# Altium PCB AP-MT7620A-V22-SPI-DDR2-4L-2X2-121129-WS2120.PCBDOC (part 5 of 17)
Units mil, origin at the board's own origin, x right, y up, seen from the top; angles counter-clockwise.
Board outline 7316 x 4279 mil, 4 copper layers (Top, Inner Layer 2, Inner Layer 3, Bottom), stack 35.4 mil thick; 640 components, 473 nets, 2041 pads, 2358 vias.
Unrouted connection lines stored in the file: 11.
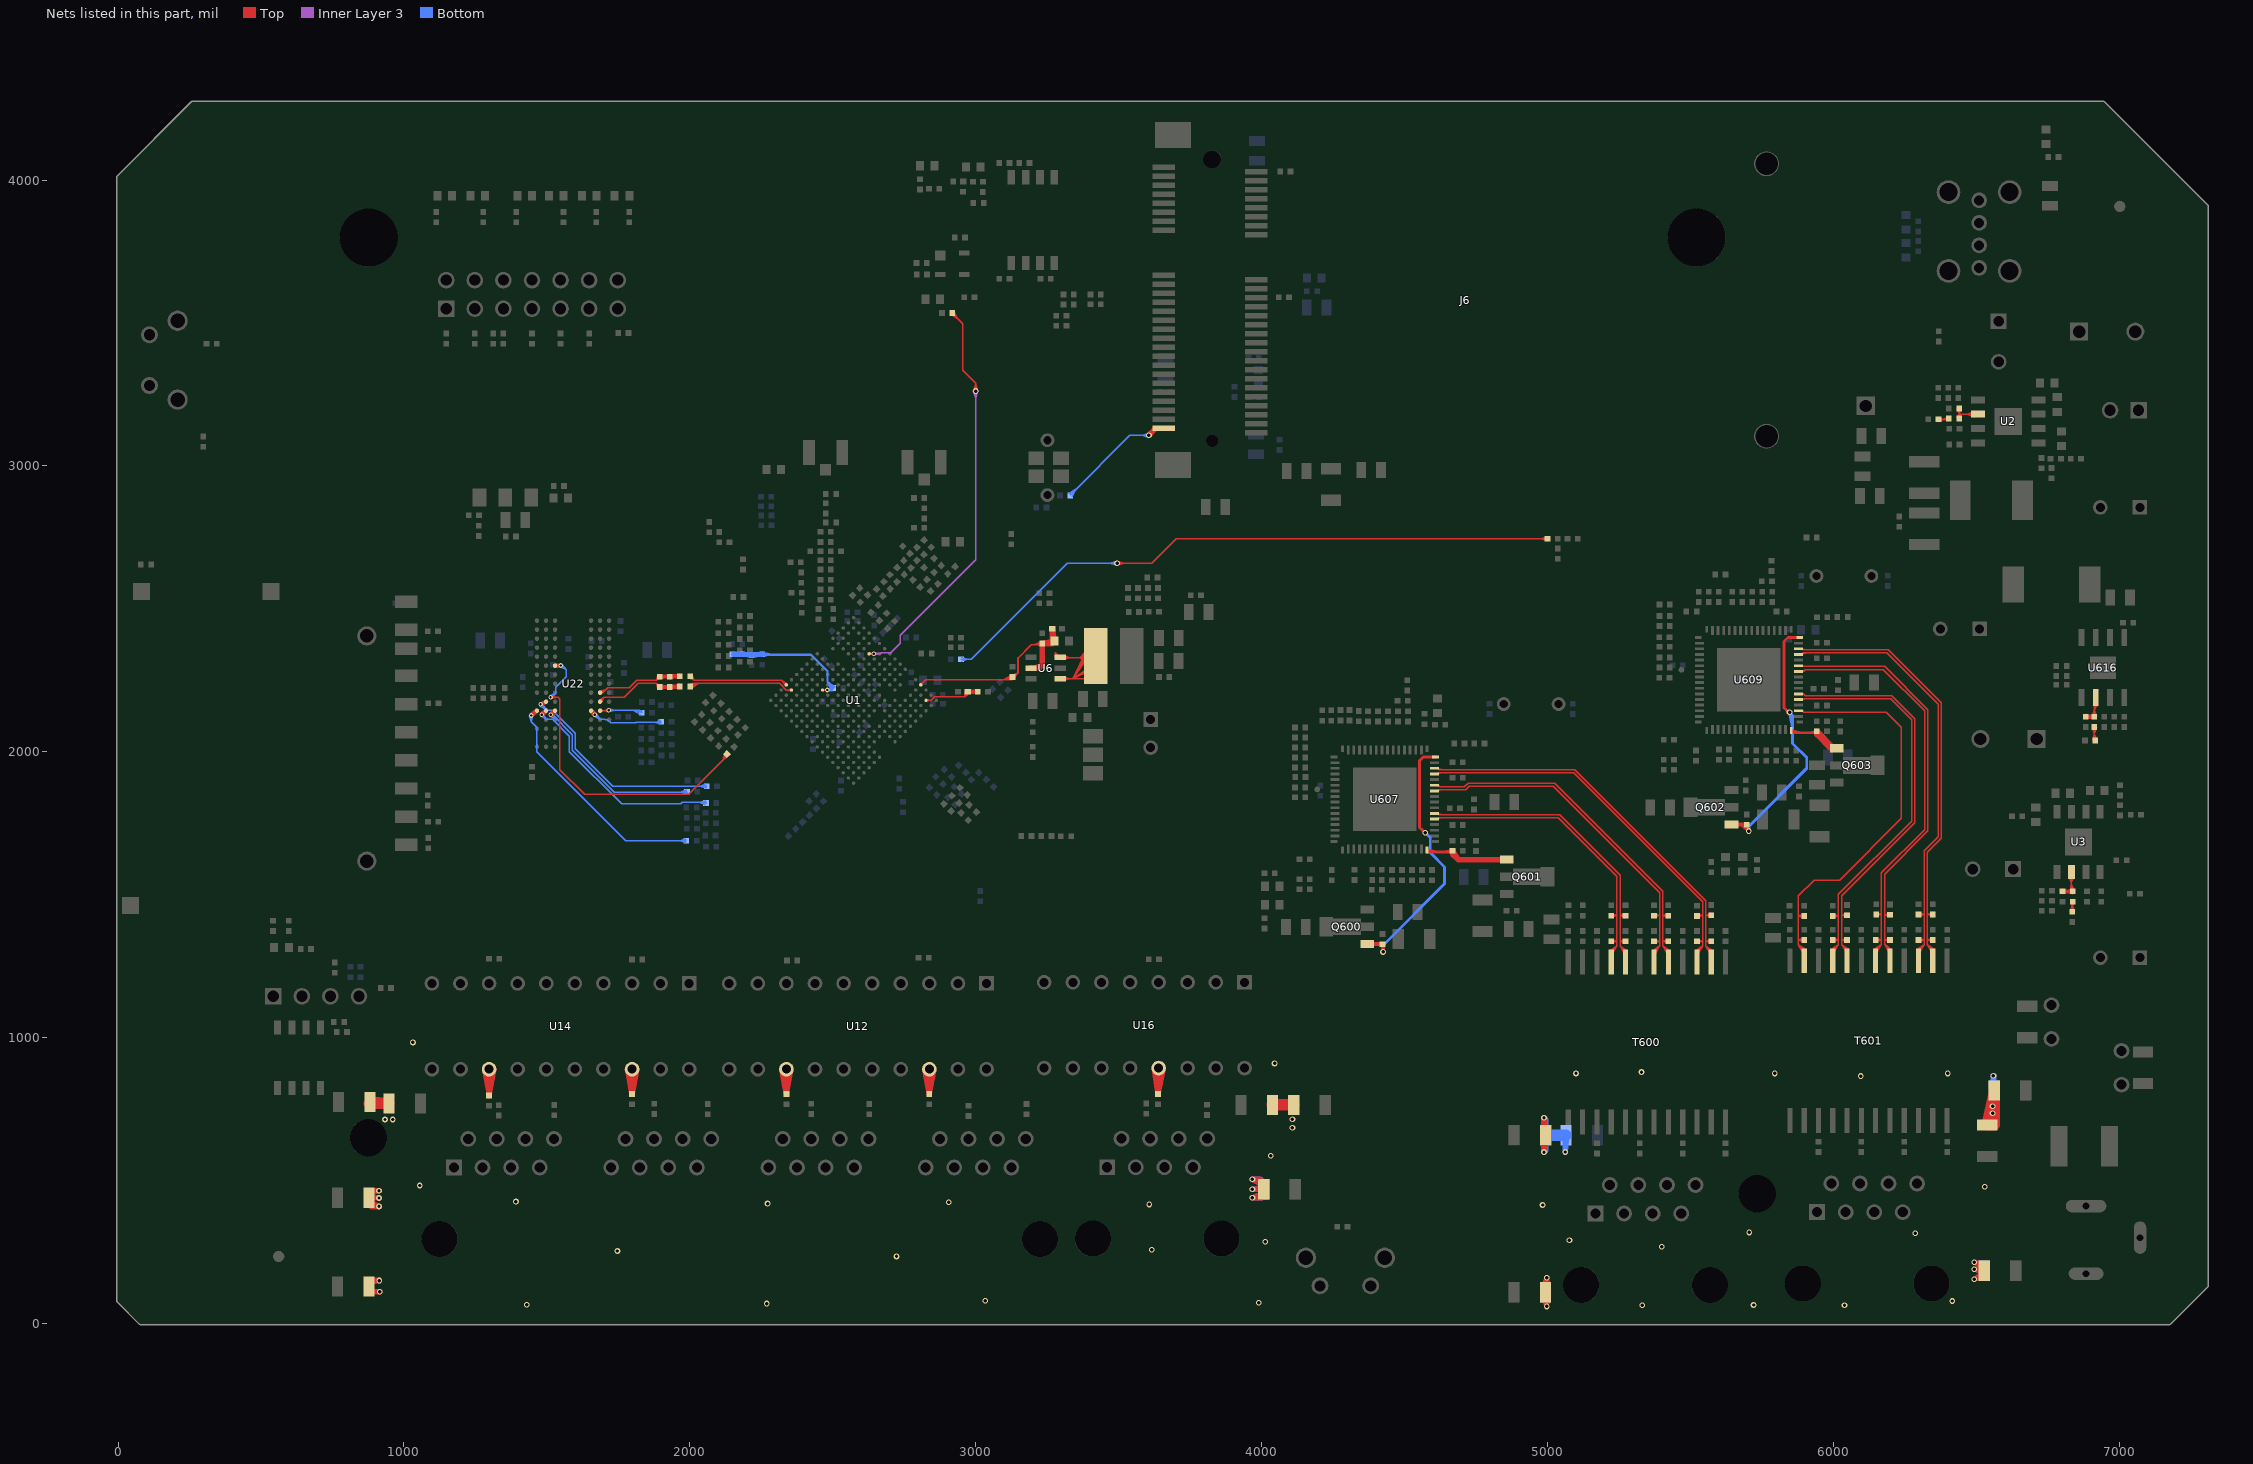
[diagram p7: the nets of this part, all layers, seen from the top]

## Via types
v1: diameter 20, hole 12, Top to Bottom, 2117 vias
v2: diameter 16, hole 8, Top to Bottom, 241 vias

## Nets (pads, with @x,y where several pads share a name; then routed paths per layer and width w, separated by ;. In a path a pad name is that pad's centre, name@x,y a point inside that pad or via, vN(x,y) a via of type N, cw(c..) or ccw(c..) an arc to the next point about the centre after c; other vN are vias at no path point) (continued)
CHANNEL_A-_2: C719.1 R792.2 T601.11 U609.19 | length 1668.2
  Top w5: U609.19@5878.22,2143.78 5892.22,2143.78 5897,2139 ; U609.19@5889.05,2143.78 5897,2139 ; T601.11@5892.8,1299.86 5878.05,1325.01 ; C719.1@5896.23,1418.71 5878.05,1427 ; R792.2@5896.28,1334.72 5878.05,1343.01 ; C719.1@5896.96,1433.43 5878.05,1427 ; R792.2@5897.02,1349.44 5878.05,1343.01 ; T601.11@5898.05,1269.54 5898.05,1305.01 5878.05,1325.01 ; T601.11@5898.05,1303.79 5878.05,1325.01 ; T601.11@5902.28,1308.79 5878.05,1325.01 ; 5878.05,1325.01 5878.05,1343.01 ; 5878.05,1343.01 5898.05,1343.01 R792.2@5898.05,1342.01 5878.05,1343.01 ; 5878.05,1343.01 5878.05,1427 ; 5878.05,1427 5898,1427 C719.1@5898,1426 5878.05,1427 ; 5878.05,1427 5878.05,1496.5 5932.55,1551 5938.55,1551 6021.76,1551 6238,1767.24 6238,2085.5 6184.5,2139 5897,2139
CHANNEL_B+: C708.1 R785.2 T600.9 U607.21 | length 1317.7
  Top w5: U607.21@4604.22,1765.15 4617.09,1765.15 4620.99,1769.05 ; 4635.41,1769.05 U607.21@4615.05,1765.15 ; T600.9@5218.82,1303.79 5243.05,1320.01 ; T600.9@5223.05,1264.54 5223.05,1300.01 5243.05,1320.01 ; T600.9@5223.05,1298.79 5243.05,1320.01 ; R785.2@5224.08,1344.44 5243.05,1338.01 ; C708.1@5224.08,1434.43 5243.05,1428 ; R785.2@5224.82,1329.72 5243.05,1338.01 ; C708.1@5224.82,1419.71 5243.05,1428 ; T600.9@5228.3,1294.86 5243.05,1320.01 ; U607.21@4615.05,1765.15 4620.99,1769.05 ; U607.21@4615.05,1765.15 4620.99,1769.05 ; 4620.99,1769.05 5037.99,1769.05 5243.05,1563.99 5243.05,1428 ; 5243.05,1320.01 5243.05,1338.01 ; 5243.05,1338.01 5223.05,1338.01 R785.2@5223.05,1337.01 5243.05,1338.01 ; 5243.05,1338.01 5243.05,1428 ; 5243.05,1428 5223.05,1428 C708.1@5223.05,1427 5243.05,1428
CHANNEL_B+_2: C720.1 R793.2 T601.9 U609.21 | length 1647.5
  Top w5: U609.21@5878.22,2183.15 5898.35,2183.15 ; U609.21@5889.05,2183.15 5898.35,2183.15 ; T601.9@5993.82,1308.79 6018.05,1325.01 ; T601.9@5998.05,1269.54 5998.05,1305.01 6018.05,1325.01 ; T601.9@5998.05,1303.79 6018.05,1325.01 ; C720.1@5999.03,1433.43 6018,1427 ; R793.2@5999.09,1349.44 6018,1343.01 ; C720.1@5999.77,1418.71 6018,1427 ; R793.2@5999.83,1334.72 6018,1343.01 ; T601.9@6003.3,1299.86 6018.05,1325.01 ; 5898.35,2183.15 5900.7,2185.5 6200.22,2185.5 6274,2111.72 6274,1757.06 6018.05,1501.1 6018.05,1500.05 6018,1500 6018,1427 ; 6018.02,1337.5 6018.05,1325.01 ; 6018.02,1337.5 6018,1343.01 ; 6018.02,1337.5 6018,1414.5 6018,1427 ; 6018,1343.01 5998.05,1343.01 R793.2@5998.05,1342.01 6018,1343.01 ; 6018,1427 5999,1427 C720.1@5998,1426 6018,1427
CHANNEL_B-: C709.1 R786.2 T600.8 U607.22 | length 1328.9
  Top w5: U607.22@4604.22,1784.84 4617.2,1784.84 4621.99,1780.05 ; 4635.63,1780.05 U607.22@4615.05,1784.84 ; T600.8@5267.7,1295.01 5254.05,1320.01 ; R786.2@5271.19,1329.74 5254.05,1338.01 ; C709.1@5271.19,1419.73 5254.05,1428 ; R786.2@5271.96,1344.43 5254.05,1338.01 ; C709.1@5271.96,1434.42 5254.05,1428 ; T600.8@5273.05,1264.54 5273.05,1301.01 5254.05,1320.01 ; T600.8@5273.05,1298.79 5254.05,1320.01 ; T600.8@5277.4,1303.7 5254.05,1320.01 ; U607.22@4615.05,1784.84 4621.99,1780.05 ; U607.22@4615.05,1784.84 4621.99,1780.05 ; 4621.99,1780.05 5042.55,1780.05 5254.05,1568.55 5254.05,1428 ; 5254.05,1320.01 5254.05,1338.01 ; 5254.05,1338.01 5273.05,1338.01 R786.2@5273.05,1337.01 5254.05,1338.01 ; 5254.05,1338.01 5254.05,1428 ; 5254.05,1428 5273.05,1428 C709.1@5273.05,1427 5254.05,1428
CHANNEL_B-_2: C721.1 R794.2 T601.8 U609.22 | length 1659
  Top w5: U609.22@5878.22,2202.84 5895.5,2202.84 ; T601.8@6042.7,1300.01 6029.05,1325.01 ; R794.2@6046.19,1334.74 6029.05,1343.01 ; C721.1@6046.52,1420.65 6029,1428 ; C721.1@6046.52,1435.35 6029,1428 ; R794.2@6046.96,1349.43 6029.05,1343.01 ; C721.1@6048,1428 6029,1428 ; T601.8@6048.05,1269.54 6048.05,1306.01 6029.05,1325.01 ; T601.8@6048.05,1303.79 6029.05,1325.01 ; T601.8@6052.4,1308.7 6029.05,1325.01 ; U609.22@5889.05,2202.84 5895.5,2202.84 ; U609.22@5889.05,2202.84 5901.84,2196.5 ; U609.22@5889.05,2202.84 5895.5,2202.84 ; 5895.5,2202.84 5901.84,2196.5 ; 5901.84,2196.5 6204.78,2196.5 6285,2116.28 6285,1752.5 6029,1496.5 6029,1428 ; 6029,1428 6029,1412.5 6029.05,1334 ; 6029.05,1325.01 6029.05,1334 ; 6029.05,1334 6029.05,1343.01 ; 6029.05,1343.01 6048.05,1343.01 R794.2@6048.05,1342.01 6029.05,1343.01
CHANNEL_C+: C710.1 R787.2 T600.6 U607.26 | length 1487
  Top w5: U607.26@4604.22,1863.58 4617.52,1863.58 4620.94,1867 ; 4635.24,1867 U607.26@4615.05,1863.58 ; T600.6@5368.69,1303.68 5393.05,1321.01 ; T600.6@5373.05,1264.54 5373.05,1301.01 5393.05,1321.01 ; T600.6@5373.05,1298.79 5393.05,1321.01 ; R787.2@5374.08,1344.44 5393.05,1338.01 ; C710.1@5374.08,1434.43 5393.05,1428 ; R787.2@5374.82,1329.72 5393.05,1338.01 ; C710.1@5374.82,1419.71 5393.05,1428 ; T600.6@5378.37,1294.96 5393.05,1321.01 ; U607.26@4615.05,1863.58 4620.94,1867 ; U607.26@4615.05,1863.58 4620.94,1867 ; 4620.94,1867 4714.02,1867 4727.02,1880 5020.4,1880 5393.05,1507.35 5393.05,1428 ; 5393.05,1321.01 5393.05,1338.01 ; 5393.05,1338.01 5373.05,1338.01 R787.2@5373.05,1337.01 5393.05,1338.01 ; 5393.05,1338.01 5393.05,1428 ; 5393.05,1428 5373.05,1428 C710.1@5373.05,1427 5393.05,1428
CHANNEL_C+_2: C722.1 R799.2 T601.6 U609.26 | length 1722
  Top w5: U609.26@5878.22,2281.58 5896.08,2281.58 ; T601.6@6143.68,1308.68 6168,1326 ; T601.6@6148.05,1269.54 6148.05,1306.05 6168,1326 ; T601.6@6148.05,1303.79 6168,1326 ; R799.2@6149.09,1349.44 6168,1343 ; R799.2@6149.82,1334.72 6168,1343 ; C722.1@6151.15,1438.41 6168,1432 ; C722.1@6151.96,1423.76 6168,1432 ; T601.6@6153.38,1299.97 6168,1326 ; U609.26@5889.05,2281.58 5896.08,2281.58 ; U609.26@5889.05,2281.58 5902.5,2288 ; U609.26@5889.05,2281.58 5896.08,2281.58 ; 5896.08,2281.58 5902.5,2288 ; 5902.5,2288 6175.47,2288 6320,2143.47 6320,1728.28 6168,1576.28 6168,1432 ; 6168,1326 6168,1343 ; 6168,1343 6148.05,1343.01 R799.2@6148.05,1342.01 6168,1343 ; 6168,1343 6168,1432 ; 6168,1432 6150,1432 C722.1@6150,1431 6168,1432
CHANNEL_C-: C711.1 R788.2 T600.5 U607.27 | length 1473.4
  Top w5: U607.27@4604.22,1883.26 4604.43,1883.05 4617.99,1883.05 4623.04,1878 ; U607.27@4615.05,1883.26 4623.04,1878 ; T600.5@5417.55,1295.22 5404.05,1322.01 ; R788.2@5421.19,1329.74 5404.05,1338.01 ; C711.1@5421.19,1419.73 5404.05,1428 ; R788.2@5421.96,1344.43 5404.05,1338.01 ; C711.1@5421.96,1434.42 5404.05,1428 ; T600.5@5423.05,1264.54 5423.05,1303.01 5404.05,1322.01 ; T600.5@5423.05,1298.79 5404.05,1322.01 ; T600.5@5427.64,1303.47 5404.05,1322.01 ; 4623.04,1878 4709.46,1878 4722.46,1891 5024.96,1891 5404.05,1511.91 5404.05,1428 ; 5404.05,1322.01 5404.05,1338.01 ; 5404.05,1338.01 5423.05,1338.01 R788.2@5423.05,1337.01 5404.05,1338.01 ; 5404.05,1338.01 5404.05,1428 ; 5404.05,1428 5423.05,1428 C711.1@5423.05,1427 5404.05,1428
CHANNEL_C-_2: C723.1 R800.2 T601.5 U609.27 | length 1741.2
  Top w5: U609.27@5878.22,2301.26 5878.43,2301.05 5891.99,2301.05 5894.04,2299 ; 5909.11,2299 U609.27@5889.05,2301.26 ; T601.5@6192.56,1300.21 6179,1327.06 ; C723.1@6196.13,1422.74 6179.05,1431 ; R800.2@6196.19,1334.74 6179,1343.01 ; C723.1@6196.91,1437.42 6179.05,1431 ; R800.2@6196.96,1349.43 6179,1343.01 ; T601.5@6198.05,1269.54 6198.05,1308.01 6179,1327.06 ; T601.5@6198.05,1303.79 6179,1327.06 ; T601.5@6202.64,1308.47 6179,1327.06 ; U609.27@5889.05,2301.26 5894.04,2299 ; U609.27@5889.05,2301.26 5894.04,2299 ; 5894.04,2299 6180.03,2299 6331,2148.03 6331,1723.72 6179,1571.72 6179,1430.95 ; 6179,1327.06 6179,1343.01 ; 6179,1343.01 6198.05,1343.01 R800.2@6198.05,1342.01 6179,1343.01 ; 6179,1343.01 6179,1430.95 ; 6179,1430.95 6179.05,1431 ; 6179.05,1431 6198,1431 C723.1@6198,1430 6179.05,1431
CHANNEL_D+: C712.1 R789.2 T600.3 U607.29 | length 1636.2
  Top w5: U607.29@4604.22,1922.63 4616,1922.63 4620.37,1927 ; 4635.52,1927 U607.29@4615.05,1922.63 ; T600.3@5518.69,1303.68 5543.05,1321.01 ; T600.3@5523.05,1264.54 5523.05,1301.01 5543.05,1321.01 ; T600.3@5523.05,1298.79 5543.05,1321.01 ; C712.1@5523.28,1433.49 5543.05,1429 ; R789.2@5524.08,1344.44 5543.05,1338.01 ; R789.2@5524.82,1329.72 5543.05,1338.01 ; C712.1@5525.46,1418.92 5543.05,1429 ; T600.3@5528.37,1294.96 5543.05,1321.01 ; U607.29@4615.05,1922.63 4620.37,1927 ; U607.29@4615.05,1922.63 4620.37,1927 ; 4620.37,1927 5091.5,1927 5543.05,1475.45 5543.05,1429 ; 5543.05,1321.01 5543.05,1338.01 ; 5543.05,1338.01 5523.05,1338.01 R789.2@5523.05,1337.01 5543.05,1338.01 ; 5543.05,1338.01 5543.05,1429 ; 5543.05,1429 5523,1429 C712.1@5523,1426 5543.05,1429
CHANNEL_D+_2: C724.1 R801.2 T601.3 U609.29 | length 1780.6
  Top w5: U609.29@5878.22,2340.63 5878.64,2341.05 5889.99,2341.05 5894.99,2346.05 ; 5909.78,2346.05 U609.29@5889.05,2340.63 ; T601.3@6293.69,1308.68 6318.05,1326.01 ; T601.3@6298.05,1269.54 6298.05,1306.01 6318.05,1326.01 ; T601.3@6298.05,1303.79 6318.05,1326.01 ; C724.1@6299.03,1438.43 6318.05,1432 ; R801.2@6299.08,1349.44 6318.05,1343.01 ; C724.1@6299.77,1423.71 6318.05,1432 ; R801.2@6299.82,1334.72 6318.05,1343.01 ; T601.3@6303.37,1299.96 6318.05,1326.01 ; U609.29@5889.05,2340.63 5894.99,2346.05 ; U609.29@5889.05,2340.63 5894.99,2346.05 ; 5894.99,2346.05 6187.67,2346.05 6367,2166.72 6367,1702.5 6318.05,1653.55 6318.05,1432 ; 6318.05,1326.01 6318.05,1343.01 ; 6318.05,1343.01 6318.05,1432 ; 6318.05,1343.01 6298.05,1343.01 R801.2@6298.05,1342.01 6318.05,1343.01 ; 6318.05,1432 6298,1432 C724.1@6298,1431 6318.05,1432
CHANNEL_D-: C713.1 R790.2 T600.2 U607.30 | length 1640.4
  Top w5: U607.30@4604.22,1942.32 4604.95,1943.05 4615.99,1943.05 4621.04,1938 ; 4635.51,1938 U607.30@4615.05,1942.32 ; T600.2@5567.7,1295.01 5554.05,1320.01 ; C713.1@5571.13,1420.74 5554.05,1429 ; R790.2@5571.19,1329.74 5554.05,1338.01 ; C713.1@5571.91,1435.42 5554.05,1429 ; R790.2@5571.96,1344.43 5554.05,1338.01 ; T600.2@5573.05,1264.54 5573.05,1301.01 5554.05,1320.01 ; T600.2@5573.05,1298.79 5554.05,1320.01 ; T600.2@5577.4,1303.7 5554.05,1320.01 ; U607.30@4615.05,1942.32 4621.04,1938 ; U607.30@4615.05,1942.32 4621.04,1938 ; 4621.04,1938 5096.06,1938 5554.05,1480.01 5554.05,1477.78 5554.05,1429 ; 5554.05,1320.01 5554.05,1338.01 ; 5554.05,1338.01 5573.05,1338.01 R790.2@5573.05,1337.01 5554.05,1338.01 ; 5554.05,1338.01 5554.05,1429 ; 5554.05,1429 5573,1429 C713.1@5573,1428 5554.05,1429
CHANNEL_D-_2: C725.1 R802.2 T601.2 U609.30 | length 1780.3
  Top w5: U609.30@5878.22,2360.32 5878.95,2361.05 5889.99,2361.05 5893.99,2357.05 ; 5909.27,2357.05 U609.30@5889.05,2360.32 ; T601.2@6342.7,1300.01 6329.05,1325.01 ; C725.1@6346.13,1423.74 6329.05,1432 ; R802.2@6346.19,1334.74 6329.05,1343.01 ; C725.1@6346.91,1438.42 6329.05,1432 ; R802.2@6346.96,1349.43 6329.05,1343.01 ; T601.2@6348.05,1269.54 6348.05,1306.01 6329.05,1325.01 ; T601.2@6348.05,1303.79 6329.05,1325.01 ; T601.2@6352.4,1308.7 6329.05,1325.01 ; U609.30@5889.05,2360.32 5893.99,2357.05 ; U609.30@5889.05,2360.32 5893.99,2357.05 ; 5893.99,2357.05 6192.23,2357.05 6378,2171.28 6378,1699.1 6378,1697.94 6329.05,1648.99 6329.05,1432 ; 6329.05,1325.01 6329.05,1343.01 ; 6329.05,1343.01 6348.05,1343.01 R802.2@6348.05,1342.01 6329.05,1343.01 ; 6329.05,1343.01 6329.05,1432 ; 6329.05,1432 6348,1432 C725.1@6348,1431 6329.05,1432
CHGND: C113.2 C116.2 C117.2 C118.2 C119.2 C120.2 C122.2 C123.2 | length 1295.6
  Top w20: C122.2@878.12,114.25 v1(915.5,111.5) 878.12,111.5 C122.2@878.12,123.9 ; C122.2@878.12,130 C122.2@878.12,123.9 ; C122.2@878.12,145.75 v1(914,150.5) 881.7,150.5 878.12,146.92 C122.2@878.12,123.9 ; C116.2@878.12,424.25 v1(913,410) 887,410 887,431.12 C116.2@878.12,440 ; C116.2@878.12,455.75 v1(913,465) 884.5,465 878.12,458.62 C116.2@878.12,440 ; C120.2@878.12,770 878.12,772 C120.2@881.62,775.5 ; v1(913,439.5) 908,440 C116.2@878.12,440 ; C117.2@4007.88,454.25 v1(3968,440) 4000.3,440 C117.2@4000.3,470 ; C117.2@4007.88,485.75 v1(3968,505) 3991.7,505 4007.88,488.82 C117.2@4007.88,470 ; C117.2@4000.3,470 C117.2@4007.88,470 ; C117.2@4000.3,470 v1(3968,470) C117.2@4007.88,470
  Top w40: C120.2@878.12,770 C113.2@947.88,770 C120.2@881.62,775.5 ; C123.2@4038.12,765 C119.2@4112.88,765 C123.2@4038.12,765
  Bottom w20: C118.2@4007.88,454.25 v1(3968,440) 4000.6,440 4005.11,444.51 C118.2@4005.11,470 ; C118.2@4007.88,485.75 v1(3968,505) 3996.5,505 C118.2@3996.5,470 ; C118.2@3996.5,470 v1(3968,470) C118.2@4007.88,470 C118.2@4005.11,470 ; C118.2@3996.5,470 C118.2@4005.11,470
  other v1: 1430,66 2269,70 3990,73 3034,80 2723,235 1747,254 3616,258 4013,286 3607,417 2272,420 2906,425 1392,427 1055,483 4032,587 4108,685 934,714 961,714 4108,715 4045.5,910 1031.5,983.5
CHGND_GE_A: C729.2 C731.2 C732.2 C733.2 C734.2 C735.2 C810.2 C814.2 C816.2 C817.2 | length 4394.2
  Top w12: C733.2@4980.22,89.68 v1(4998,60) ; C733.2@4993.12,94.25 v1(4998,60) ; C733.2@4993.12,110 4993.4,110 4998,105.4 4998,104.6 v1(4998,60) ; C733.2@5006.78,93.47 v1(4998,60) ; C816.2@6520.49,180.77 v1(6493,155) ; C816.2@6520.49,189.23 v1(6493,215) ; C816.2@6523.35,172.09 v1(6493,190) ; C816.2@6527.16,198.67 v1(6493,190) ; C816.2@6527.88,169.25 v1(6493,155) ; C816.2@6527.88,200.75 v1(6493,215) ; C816.2@6530.67,155.85 v1(6493,155) ; C816.2@6530.67,214.15 v1(6493,215) ; v1(6493,155) 6517.7,155 6517.7,174.82 C816.2@6527.88,185 ; v1(6493,190) C816.2@6520,190 ; v1(6493,190) C816.2@6527.88,185 ; v1(6493,215) 6520,215 C816.2@6520,190 ; C816.2@6520,190 6526.88,190 6527.88,189 C816.2@6527.88,185
  Top w20: C733.2@4993.12,125.75 v1(4998,160.6) C733.2@4998,104.6 ; C734.2@4993.12,644.25 v1(4988,600) C734.2@4988,667.2 ; C734.2@4993.12,660 4992.32,660.8 4988,660.8 C734.2@4988,667.2 ; C734.2@4993.12,675.75 v1(4988,720) C734.2@4988,667.2
  Top w40: C731.2@6562.88,815 C731.2@6563,805.12 ; C732.2@6538,695.12 C732.2@6563,695.12 ; C732.2@6538,695.12 C731.2@6563,805.12 ; C732.2@6538,695.12 C731.2@6562.88,799.25 ; C732.2@6538,695.12 v1(6557,736) ; C732.2@6538,695.12 v1(6557,736) ; C732.2@6538,695.12 v1(6557,760) ; C732.2@6538,695.12 v1(6557,760) ; C732.2@6538,695.12 v1(6557,760) ; C732.2@6538,695.12 v1(6557,760) ; v1(6557,736) C731.2@6563,805.12 ; v1(6557,736) C732.2@6563,695.12 ; v1(6557,736) C731.2@6563,805.12 ; v1(6557,736) C732.2@6563,695.12 ; v1(6557,736) C731.2@6562.88,799.25 ; v1(6557,736) C731.2@6562.88,799.25 ; v1(6557,760) C731.2@6563,805.12 ; v1(6557,760) C732.2@6563,695.12 ; v1(6557,760) C731.2@6563,805.12 ; v1(6557,760) C732.2@6563,695.12 ; v1(6557,760) C731.2@6562.88,799.25 ; v1(6557,760) C731.2@6562.88,799.25 ; v1(6557,760) C731.2@6563,805.12 ; v1(6557,760) C732.2@6563,695.12 ; v1(6557,760) C731.2@6563,805.12 ; v1(6557,760) C732.2@6563,695.12 ; v1(6557,760) C731.2@6562.88,799.25 ; v1(6557,760) C731.2@6562.88,799.25 ; C731.2@6562.88,799.25 C732.2@6563,695.12 ; C732.2@6563,695.12 C731.2@6563,805.12
  Bottom w12: C810.2@4980.22,89.68 v1(4998,60) ; C810.2@4980.19,130.25 v1(4998,160.6) ; C810.2@4993.12,94.25 v1(4998,60) ; C810.2@4993.12,110 4994.7,110 C810.2@4996.95,107.75 ; C810.2@4993.12,125.75 v1(4998,160.6) ; C810.2@5006.78,93.47 v1(4998,60) ; C810.2@5006.78,126.52 v1(4998,160.6) ; C729.2@6520.49,180.77 v1(6493,155) ; C729.2@6520.49,189.23 v1(6493,215) ; C729.2@6523.35,172.09 v1(6493,190) ; C729.2@6527.16,198.67 v1(6493,190) ; C729.2@6527.88,169.25 v1(6493,155) ; C729.2@6527.88,200.75 v1(6493,215) ; C729.2@6530.67,155.85 v1(6493,155) ; C729.2@6530.67,214.15 v1(6493,215) ; C814.2@6556.5,808.62 C814.2@6562.88,815 ; C810.2@4996.95,107.75 4998,108.8 v1(4998,160.6) ; C810.2@4996.95,107.75 4998,106.7 v1(4998,60) ; v1(6493,155) 6522.4,155 6522.4,190 C729.2@6526.98,190 ; v1(6493,190) C729.2@6526.98,190 ; v1(6493,190) C729.2@6527.88,185 C729.2@6527.88,190.9 ; v1(6493,215) 6527.1,215 6527.88,214.22 C729.2@6527.88,190.9 ; C729.2@6526.98,190 C729.2@6527.88,190.9
  Bottom w20: C735.2@5061.8,658.56 v1(5061.8,600.4) C735.2@5065,642.81 ; C814.2@6556.5,808.62 C814.2@6557,808.12 ; C814.2@6562.88,799.25 v1(6557,760) C814.2@6557,808.12 ; C814.2@6562.88,830.75 v1(6560,867) 6560,811.12 C814.2@6557,808.12 ; v1(4988,600) v1@4993.8,605.8 ; v1(4988,600) 4993.8,642.81 v1@4993.8,605.8 ; v1(4988,600) C817.2@4993.8,658.56 ; v1(4988,720) v1@4993.8,714.2 ; v1(4988,720) C817.2@4993.8,658.56 ; v1(4988,720) 4993.8,674.31 v1@4993.8,714.2 ; v1@4993.8,605.8 C817.2@4993.8,658.56 ; C817.2@4993.8,658.56 v1@4993.8,714.2
  Bottom w40: C817.2@4993.8,658.56 5061.8,658.56 C735.2@5065,658.56 C817.2@4993.8,658.56
  other v1: 5332,64 6039,64 5721,65 6416,79 5400,269 5077,292 6287,316 5706,319 4983,415 6530,479 6096,866 5100,875 5795,875 6400,875 5329,880
CLK_25M_1-CPU-RT0: R831.2 R832.2 | length 2486.2
  Top w5: v1(3494.5,2659.5) 3616,2659.5 3701.5,2745 R832.2@5000,2745 4975,2745 ; v1@3495.54,2652.07 3521.5,2659.5 v1@3495.54,2666.93 ; R832.2@4998.88,2737.58 4975,2745 ; R832.2@4998.88,2752.42 4975,2745
  Bottom w5: R831.2@2948.5,2323.5 2984,2323.5 3319.5,2659.5 v1(3494.5,2659.5) 3467.5,2659.5 ; R831.2@2949.62,2316.08 2973.5,2323.5 R831.2@2949.62,2330.92 ; v1@3493.46,2652.07 3467.5,2659.5 ; v1@3493.46,2666.93 3467.5,2659.5
CLK_A_IN: J6.51 R810.2 | length 1637.1
  Top w4.5: v1@3599.91,3111.79 J6.51@3619.74,3130.76 ; v1@3600.52,3112.48 J6.51@3623.28,3129.73 ; v1@3601,3112.92 J6.51@3626.02,3129.01 ; v1@3601.12,3113.02 J6.51@3626.75,3128.82 ; v1@3601.54,3113.34 J6.51@3627.93,3127.16 ; v1@3602.43,3113.88 J6.51@3629.15,3123.4 ; v1@3603.29,3108.79 J6.51@3619.74,3130.76 ; v1@3603.53,3109.11 J6.51@3623.28,3129.73 ; v1@3603.72,3109.32 J6.51@3626.02,3129.01 ; v1@3603.77,3109.36 J6.51@3626.75,3128.82 ; v1@3603.93,3109.51 J6.51@3627.93,3127.16 ; v1@3604.28,3109.76 J6.51@3629.15,3123.4 ; v1@3608.03,3104.46 J6.51@3629.15,3123.4 ; v1@3608.33,3104.73 J6.51@3627.93,3127.16 ; v1@3608.47,3104.89 J6.51@3626.75,3128.82 ; v1@3608.52,3104.95 J6.51@3626.02,3129.01 ; v1@3608.7,3105.18 J6.51@3623.28,3129.73 ; v1@3608.91,3105.54 J6.51@3619.74,3130.76 ; v1@3611.3,3101.35 J6.51@3629.15,3123.4 ; v1@3611.94,3102.03 J6.51@3627.93,3127.16 ; v1@3612.26,3102.43 J6.51@3626.75,3128.82 ; v1@3612.36,3102.58 J6.51@3626.02,3129.01 ; v1@3612.75,3103.19 J6.51@3623.28,3129.73 ; v1@3613.19,3104.11 J6.51@3619.74,3130.76 ; J6.51@3622.21,3135.91 v1@3611.46,3113.54 ; J6.51@3626.09,3133.59 v1@3611.46,3113.54 ; J6.51@3628.47,3131.61 v1@3611.46,3113.54 ; J6.51@3630.59,3129.36 v1@3611.46,3113.54 ; J6.51@3633.14,3125.63 v1@3611.46,3113.54 ; J6.51@3658,3131.61 3629.54,3131.61 3605.46,3107.54 v1(3606,3107) ; v1(3606,3107) J6.51@3626.75,3128.82 ; v1(3606,3107) J6.51@3629.15,3123.4 ; v1(3606,3107) J6.51@3619.74,3130.76 ; v1(3606,3107) J6.51@3627.93,3127.16 ; v1(3606,3107) J6.51@3623.28,3129.73 ; v1(3606,3107) J6.51@3626.02,3129.01
  Bottom w4.5: 3539,3107 v1(3606,3107) 3580.5,3107 ; v1@3604.82,3099.34 3580.5,3107 ; v1@3604.82,3114.66 3580.5,3107 ; v1@3605.79,3103.76 3580.5,3107 ; v1@3605.79,3110.24 3580.5,3107
  Bottom w5: R810.2@3326.14,2902.71 3350.6,2918.6 ; R810.2@3337.16,2892.72 3350.6,2918.6 ; 3539,3107 3330,2898 3330,2897 R810.2@3331,2897 3350.6,2918.6
CLK_N: C127.2 R100.2 R150.2 U22.K8 | length 1348.5
  Top w4.5: U22.K8@1682.61,2179.78 1701.42,2190.7 ; U22.K8@1686.04,2175.33 1701.42,2190.7 ; U22.K8@1690.5,2171.9 1701.42,2190.7 ; C127.2@1888.49,2222.8 1882,2240 ; C127.2@1892.51,2224.91 1882,2240 ; C127.2@1895,2227 1882,2240 ; C127.2@1897.09,2229.49 1882,2240 ; C127.2@1899.2,2233.51 1882,2240 ; 1701.42,2190.7 1770.7,2190.7 1820,2240 1882,2240
  Top w5: C127.2@1894.75,2219.5 1920.17,2222.4 ; C127.2@1894.73,2234.5 1920.35,2231.66 ; C127.2@1897.41,2219.9 1920.35,2231.66 ; C127.2@1897.42,2234.1 1920.17,2222.4 ; R150.2@1929.23,2219.58 1905.36,2227 ; R150.2@1929.23,2234.42 1905.36,2227 ; R150.2@1931.18,2234.45 1955.38,2228 ; R150.2@1931.77,2219.64 1955.38,2228 ; R100.2@1962.58,2235.69 1940.4,2222.69 ; R100.2@1963.32,2221.53 R150.2@1940.06,2232.09 ; R100.2@1963.87,2236.08 1940.41,2227.4 ; R100.2@1964.05,2236.12 1940.37,2228 ; R100.2@1964.48,2221.29 1940.37,2228 ; R100.2@1964.66,2221.27 1940.41,2227.4 ; R100.2@1965.27,2236.24 R150.2@1940.06,2232.09 ; R100.2@1966.07,2221.27 1940.4,2222.69 ; C127.2@1895,2227 R150.2@1930.36,2227 ; C127.2@1895,2227 1920.17,2222.4 ; C127.2@1895,2227 1905.36,2227 ; C127.2@1895,2227 1920.35,2231.66 ; C127.2@1895,2227 1905.36,2227 ; C127.2@1895,2227 1920,2227 ; C127.2@1895,2227 1905.36,2227 ; C127.2@1897.72,2220.01 1905.36,2227 ; C127.2@1897.72,2220.01 1905.36,2227 ; C127.2@1897.72,2220.01 1905.36,2227 ; C127.2@1897.72,2233.99 1905.36,2227 ; C127.2@1897.72,2233.99 1905.36,2227 ; C127.2@1897.72,2233.99 1905.36,2227 ; 1905.36,2227 R150.2@1930.36,2227 ; 1920,2227 1896.12,2234.42 1920,2227 ; 1920,2227 1896.12,2219.58 1920,2227 ; R150.2@1930.36,2227 1930.36,2228 1965.65,2228 1966.39,2228.74 R100.2@1965.39,2228.74 ; R150.2@1930.36,2227 1955.38,2228 ; R150.2@1940.06,2232.09 R100.2@1965.39,2228.74 ; 1940.37,2228 R100.2@1965.39,2228.74 ; 1940.4,2222.69 R100.2@1965.39,2228.74 ; 1940.41,2227.4 R100.2@1965.39,2228.74 ; 1955.38,2228 R100.2@1963.1,2221.59 ; 1955.38,2228 R100.2@1962.08,2235.47 ; 1955.38,2228 R100.2@1965.39,2228.74 ; 1955.38,2228 R100.2@1963.1,2221.59 ; 1955.38,2228 R100.2@1962.08,2235.47 ; 1955.38,2228 R100.2@1965.39,2228.74 ; 1955.38,2228 R100.2@1963.1,2221.59 ; 1955.38,2228 R100.2@1962.08,2235.47 ; 1955.38,2228 R100.2@1965.39,2228.74
CLK_P: C127.1 R99.2 R150.1 U22.J8 | length 1354
  Top w4.5: U22.J8@1683.95,2212.04 1707.93,2218.65 ; U22.J8@1689.26,2202.21 1707.93,2218.65 ; C127.1@1888.49,2267.21 1881.97,2249.97 ; C127.1@1892.51,2265.09 1881.97,2249.97 ; C127.1@1895,2263 1881.97,2249.97 ; C127.1@1897.09,2260.51 1881.97,2249.97 ; C127.1@1899.21,2256.49 1881.97,2249.97 ; U22.J8@1686.04,2206.82 1696.11,2206.82 ; U22.J8@1686.04,2206.82 1707.93,2218.65 ; U22.J8@1686.04,2206.82 1696.11,2206.82 ; U22.J8@1686.04,2206.82 1696.11,2206.82 ; 1696.11,2206.82 1712.79,2223.5 1788.35,2223.5 1815.16,2249.97 1881.97,2249.97 ; 1696.11,2206.82 1687.61,2212.22 1696.11,2206.82 ; 1696.11,2206.82 1687.61,2201.42 1696.11,2206.82
  Top w5: C127.1@1894.75,2255.5 1920.17,2258.4 ; C127.1@1894.73,2270.5 1920.35,2267.66 ; C127.1@1897.41,2255.9 1920.35,2267.66 ; C127.1@1897.42,2270.1 1920.17,2258.4 ; R150.1@1929.23,2255.58 1905.36,2263 ; R150.1@1929.23,2270.42 1905.36,2263 ; R150.1@1929.76,2270.48 R99.2@1957.47,2268.9 ; R150.1@1930.17,2255.5 R99.2@1955.77,2258.61 ; R150.1@1931.18,2255.55 1955.38,2262 ; R150.1@1931.33,2270.44 R99.2@1956.54,2263.35 ; R150.1@1931.53,2255.59 R99.2@1956.54,2263.35 ; R150.1@1931.77,2270.36 1955.38,2262 ; R150.1@1932.69,2270.13 R99.2@1955.77,2258.61 ; R150.1@1932.93,2255.95 R99.2@1957.47,2268.9 ; R99.2@1963.66,2271.39 R150.1@1940.29,2262 ; R99.2@1964.89,2256.61 R150.1@1940.29,2262 ; C127.1@1895,2263 1929.36,2263 R150.1@1930.36,2262 ; C127.1@1895,2263 1920.17,2258.4 ; C127.1@1895,2263 1905.36,2263 ; C127.1@1895,2263 1920.35,2267.66 ; C127.1@1895,2263 1905.36,2263 ; C127.1@1895,2263 1920,2263 ; C127.1@1895,2263 1905.36,2263 ; C127.1@1897.72,2256.01 1905.36,2263 ; C127.1@1897.72,2256.01 1905.36,2263 ; C127.1@1897.72,2256.01 1905.36,2263 ; C127.1@1897.72,2269.99 1905.36,2263 ; C127.1@1897.72,2269.99 1905.36,2263 ; C127.1@1897.72,2269.99 1905.36,2263 ; 1905.36,2263 R150.1@1930.36,2263 ; 1920,2263 1896.12,2270.42 1920,2263 ; 1920,2263 1896.12,2255.58 1920,2263 ; R150.1@1930.36,2262 R150.1@1930.36,2263 ; R150.1@1930.36,2262 1966.39,2262 1966.39,2264.09 R99.2@1965.39,2264.09 R150.1@1940.29,2262 ; R150.1@1930.36,2263 1955.38,2262 ; R150.1@1930.36,2263 R99.2@1955.77,2258.61 ; R150.1@1930.36,2263 R99.2@1957.47,2268.9 ; R150.1@1930.36,2263 R99.2@1956.54,2263.35
CMT0_4-ETHERNET: R118.2 U14.13 | length 348.8
  Top w20: U14.13@1282.47,888.58 R118.2@1298,804.41 ; R118.2@1298,798 U14.13@1298,890 R118.2@1298,804.41 ; U14.13@1313.53,888.58 R118.2@1298,804.41
CMT1_4-ETHERNET: R115.2 U14.18 | length 343.8
  Top w20: U14.18@1782.47,888.58 R115.2@1798,804.41 ; R115.2@1798,803 U14.18@1798,890 R115.2@1798,804.41 ; U14.18@1813.53,888.58 R115.2@1798,804.41
CMT2_4-ETHERNET: R112.2 U12.13 | length 343.8
  Top w20: U12.13@2322.47,888.58 R112.2@2338,804.41 ; R112.2@2338,803 U12.13@2338,890 R112.2@2338,804.41 ; U12.13@2353.53,888.58 R112.2@2338,804.41
CMT3_4-ETHERNET: R109.2 U12.18 | length 343.8
  Top w20: U12.18@2822.47,888.58 R109.2@2838,804.41 ; R109.2@2838,803 U12.18@2838,890 R109.2@2838,804.41 ; U12.18@2853.53,888.58 R109.2@2838,804.41
CMT4_4-ETHERNET: R121.2 U16.13 | length 348.8
  Top w20: U16.13@3624.45,892.94 R121.2@3638,808.37 ; R121.2@3638,803 3638,892 U16.13@3640,894 R121.2@3638,808.37 ; U16.13@3655.49,892.22 R121.2@3638,808.37
COMP1_5-POWER0: C20.1 C21.1 U3.6 | length 1278.9
  Top w4.5: C21.1@6802,1512 C20.1@6837,1512 ; C21.1@6802.22,1508.76 6825.5,1512 ; C21.1@6802.22,1515.24 6825.5,1512 ; C21.1@6803.28,1504.36 6825.5,1512 ; C21.1@6803.28,1519.64 6825.5,1512 ; U3.6@6823.23,1565.36 6833,1541.58 ; U3.6@6827.58,1566.7 6833,1541.58 ; C20.1@6829.25,1511.96 6833,1536.28 ; U3.6@6833,1567.28 6833,1541.58 ; U3.6@6833,1579.39 6833,1515 6834,1515 C20.1@6837,1512 ; C20.1@6833.76,1511.68 6833,1536.28 ; C20.1@6834.44,1504.69 6813.1,1516.27 ; C20.1@6834.44,1519.31 6812.8,1507.63 ; C20.1@6835.19,1504.46 6813.41,1513.68 ; C20.1@6835.19,1519.54 6813.33,1510.31 ; C20.1@6835.72,1504.36 6813.5,1512 ; C20.1@6835.72,1519.64 6813.5,1512 ; C20.1@6836.22,1508.85 6813.1,1516.27 ; C20.1@6836.21,1515.15 6812.8,1507.63 ; C20.1@6836.28,1504.28 6813.33,1510.31 ; C20.1@6836.28,1519.72 6813.41,1513.68 ; C20.1@6836.78,1508.76 6813.5,1512 ; C20.1@6836.78,1515.24 6813.5,1512 ; C20.1@6837.01,1508.75 6813.33,1510.31 ; C20.1@6837.01,1515.25 6813.41,1513.68 ; C20.1@6837.16,1504.25 6812.8,1507.63 ; C20.1@6837.13,1519.75 6813.1,1516.27 ; C20.1@6837.36,1508.77 6812.8,1507.63 ; C20.1@6837.36,1515.23 6813.1,1516.27 ; U3.6@6838.42,1566.7 6833,1541.58 ; C20.1@6840.17,1512.74 6833,1536.28 ; U3.6@6842.77,1565.36 6833,1541.58 ; C20.1@6844.35,1514.45 6833,1536.28 ; 6812.8,1507.63 C20.1@6837,1512 ; 6813.1,1516.27 C20.1@6837,1512 ; 6813.33,1510.31 C20.1@6836.55,1515.22 ; 6813.33,1510.31 C20.1@6837,1512 ; 6813.41,1513.68 C20.1@6836.55,1508.78 ; 6813.41,1513.68 C20.1@6837,1512 ; 6813.5,1512 C20.1@6837,1512 ; 6825.5,1512 C20.1@6834.39,1504.7 ; 6825.5,1512 C20.1@6834.39,1519.3 ; 6825.5,1512 C20.1@6836.54,1508.78 ; 6825.5,1512 C20.1@6836.54,1515.22 ; 6825.5,1512 C20.1@6837,1512 ; 6825.5,1512 C20.1@6834.39,1504.7 ; 6825.5,1512 C20.1@6834.39,1519.3 ; 6825.5,1512 C20.1@6836.54,1508.78 ; 6825.5,1512 C20.1@6836.54,1515.22 ; 6825.5,1512 C20.1@6837,1512 ; 6825.5,1512 C20.1@6834.39,1504.7 ; 6825.5,1512 C20.1@6834.39,1519.3 ; 6825.5,1512 C20.1@6836.54,1508.78 ; 6825.5,1512 C20.1@6836.54,1515.22 ; 6825.5,1512 C20.1@6837,1512 ; 6825.5,1512 C20.1@6834.39,1504.7 ; 6825.5,1512 C20.1@6834.39,1519.3 ; 6825.5,1512 C20.1@6836.54,1508.78 ; 6825.5,1512 C20.1@6836.54,1515.22 ; 6825.5,1512 C20.1@6837,1512 ; 6833,1536.28 C20.1@6837,1512
COMP2_5-POWER0: C10.1 C11.1 U2.6 | length 391.2
  Top w4.5: C11.1@6432.4,3199.5 6440,3181 ; C10.1@6432.51,3168 6440,3181 ; C10.1@6436.77,3166.35 6440,3181 ; C11.1@6436.76,3200.74 6440,3181 ; C10.1@6440,3166 6440,3181 ; C10.1@6443.23,3166.35 6440,3181 ; C11.1@6443.24,3200.74 6440,3181 ; C10.1@6447.49,3168 6440,3181 ; C11.1@6447.6,3199.5 6440,3181 ; U2.6@6492.36,3171.23 6468.58,3181 ; U2.6@6492.36,3190.77 6468.58,3181 ; U2.6@6493.7,3175.58 6468.58,3181 ; U2.6@6493.7,3186.42 6468.58,3181 ; U2.6@6494.28,3181 6468.58,3181 ; U2.6@6507.67,3181 U2.6@6506.39,3181 6440,3181 ; 6440,3181 C11.1@6440,3201 6440,3181
COMP11_5-POWER0: C316.1 C318.1 U616.6 | length 1003.9
  Top w4.5: C318.1@6883,2123 C316.1@6913,2123 ; C318.1@6883.22,2119.76 C316.1@6906.5,2123 ; C318.1@6883.22,2126.24 C316.1@6906.5,2123 ; C318.1@6884.28,2115.36 C316.1@6906.5,2123 ; C318.1@6884.28,2130.64 C316.1@6906.5,2123 ; C316.1@6905.36,2124.28 6913,2146.5 ; C316.1@6909.76,2123.22 6913,2146.5 ; C316.1@6909.95,2115.88 C318.1@6889.58,2128.82 ; C316.1@6909.95,2130.12 C318.1@6889.58,2117.18 ; U616.6@6910.22,2171.54 6913,2147.48 ; C316.1@6910.97,2115.52 C318.1@6889.5,2125.37 ; C316.1@6910.97,2130.48 C318.1@6889.5,2120.63 ; C316.1@6911.72,2115.36 C318.1@6889.5,2123 ; C316.1@6911.72,2130.64 C318.1@6889.5,2123 ; C316.1@6912.01,2119.91 C318.1@6889.58,2128.82 ; C316.1@6912.01,2126.09 C318.1@6889.58,2117.18 ; C316.1@6912.45,2119.8 C318.1@6889.5,2125.37 ; C316.1@6912.45,2126.2 C318.1@6889.5,2120.63 ; C316.1@6912.5,2115.27 C318.1@6889.5,2120.63 ; C316.1@6912.5,2130.73 C318.1@6889.5,2125.37 ; C316.1@6912.78,2119.76 C318.1@6889.5,2123 ; C316.1@6912.78,2126.24 C318.1@6889.5,2123 ; C316.1@6913.1,2119.75 C318.1@6889.5,2120.63 ; C316.1@6913.1,2126.25 C318.1@6889.5,2125.37 ; C316.1@6913.57,2119.8 C318.1@6889.58,2117.18 ; C316.1@6913.57,2126.2 C318.1@6889.58,2128.82 ; C316.1@6913.64,2115.28 C318.1@6889.58,2117.18 ; C316.1@6913.64,2130.72 C318.1@6889.58,2128.82 ; U616.6@6914.74,2171.64 6913,2147.48 ; C316.1@6916.24,2123.22 6913,2146.5 ; U616.6@6918,2171.18 6913,2147.48 ; U616.6@6918,2190.67 6913,2185.67 C316.1@6913,2123 ; C316.1@6920.64,2124.28 6913,2146.5 ; U616.6@6921.17,2170.29 6913,2147.48 ; U616.6@6925.26,2168.37 6913,2147.48 ; C318.1@6889.5,2120.63 C316.1@6913,2123 ; C318.1@6889.5,2123 C316.1@6913,2123 ; C318.1@6889.5,2125.37 C316.1@6913,2123 ; C318.1@6889.58,2117.18 C316.1@6913,2123 ; C318.1@6889.58,2128.82 C316.1@6913,2123
COMPE1_5-POWER0: C20.2 R12.1 | length 233.7
  Top w4: R12.1@6828.13,1442.45 6836,1463 ; C20.2@6829.08,1474.91 6836,1453.97 ; R12.1@6832.02,1441.36 6836,1463 ; C20.2@6833,1475.82 6836,1453.97 ; R12.1@6836,1441 C20.2@6836,1475 ; C20.2@6837,1476 6836,1453.97 ; R12.1@6839.98,1441.36 6836,1463 ; C20.2@6840.96,1475.46 6836,1453.97 ; R12.1@6843.87,1442.45 6836,1463 ; C20.2@6844.79,1474.19 6836,1453.97
  Top w4.5: C20.2@6836,1475 C20.2@6837,1476
COMPE2_5-POWER0: C10.2 R7.1 | length 237.9
  Top w4: R7.1@6368,3163 C10.2@6401,3163 ; R7.1@6368.36,3159.02 6390,3163 ; R7.1@6368.36,3166.98 6390,3163 ; R7.1@6369.45,3155.13 6390,3163 ; R7.1@6369.45,3170.87 6390,3163 ; C10.2@6401.54,3173.61 6381.67,3163 ; C10.2@6403.12,3169.9 6381.67,3163 ; C10.2@6403.64,3158.01 6381.67,3163 ; C10.2@6404,3166 6381.67,3163 ; C10.2@6404.18,3162 6381.67,3163
  Top w4.5: C10.2@6401,3163 C10.2@6404,3166
COMPE11_5-POWER0: C316.2 R274.1 | length 287.3
  Top w4.5: C316.2@6905.36,2085.72 6913,2063.5 ; R274.1@6908.26,2040.29 6913,2063.77 ; C316.2@6909.76,2086.78 6913,2063.5 ; R274.1@6912.76,2039.81 6913,2063.77 ; C316.2@6916.24,2086.78 6913,2063.5 ; R274.1@6919.19,2040.62 6913,2063.77 ; C316.2@6920.64,2085.72 6913,2063.5 ; R274.1@6923.43,2042.2 6913,2063.77 ; 6913,2063.5 C316.2@6913,2087 6913,2040 R274.1@6916,2040 6913,2063.77
CPURST_N: R15.2 U1.C6 | length 1854.4
  Top w4.5: R15.2@2913.19,3528.92 2936.92,3515.08 ; R15.2@2915.78,3532.63 2936.92,3515.08 ; R15.2@2920.49,3537.1 2936.92,3515.08 ; R15.2@2924.32,3539.49 2936.92,3515.08 ; v1@2992.34,3263.18 3000,3287.5 ; v1@2996.76,3262.21 3000,3287.5 ; v1(3000,3262) 3000,3290 2955,3335 2955,3497 2917,3535 R15.2@2918,3535 2936.92,3515.08 ; v1@3003.24,3262.21 3000,3287.5 ; v1@3007.66,3263.18 3000,3287.5
  Top w8: v2@2643.36,2342.86 U1.C6@2627.29,2342.86 v2(2643.5,2343)
  Top w10: v2@2643.36,2342.86 v2(2643.5,2343)
  Inner Layer 3 w4.5: v2(2643.5,2343) 2666.96,2343 ; v2@2644.2,2337.29 2666.96,2343 ; v2@2644.2,2348.71 2666.96,2343 ; v1@2992.34,3260.82 3000,3236.5 ; v1@2996.76,3261.79 3000,3236.5 ; v1@3003.24,3261.79 3000,3236.5 ; v1@3007.66,3260.82 3000,3236.5 ; 2666.96,2343 2669.96,2346 2703,2346 2736,2379 2736,2408.16 3000,2672.16 v1(3000,3262) 3000,3236.5
CRTL12V_IP1001-2_1-CPU-RT0: C659.1 Q602.1 U609.32 | length 1262.5
  Top w10: U609.32@5875.27,2399.69 5841.69,2399.69 ; U609.32@5878.22,2399.69 5841.69,2399.69 ; 5834,2147.83 5843.69,2138.14 v1(5846.93,2138.14) 5834,2147.83 ; 5834,2147.83 5828,2153.96 5828,2386 5841.69,2399.69
  Top w15: 5681.06,1746.21 Q602.1@5643.35,1746.21 C659.1@5696.99,1745.05 ; 5681.06,1746.21 v1(5704.47,1722.8) ; 5681.06,1746.21 5653.29,1746.21 C659.1@5696.99,1745.05 ; 5681.06,1746.21 C659.1@5696.99,1745.05 ; 5681.06,1746.21 C659.1@5696.99,1745.05 ; 5681.06,1746.21 C659.1@5696.99,1745.05 ; 5681.06,1746.21 v1(5704.47,1722.8) ; C659.1@5696.99,1745.05 v1(5704.47,1722.8) ; C659.1@5696.99,1745.05 v1(5704.47,1722.8)
  Bottom w10: v1(5704.47,1722.8) 5704.47,1739.97 5906.99,1942.49 5906.99,1980.03 5857.54,2029.48 5857.54,2127.53 v1(5846.93,2138.14) 5857.54,2088
CRTL12V_IP1001_1-CPU-RT0: C653.1 Q600.1 U607.32 | length 1193.7
  Top w10: 4566.34,1981.69 U607.32@4601.27,1981.69 ; U607.32@4608.16,1981.69 4565.88,1981.69 4553,1968.8 4553,1735.01 ; 4553,1735.01 4570,1718 v1(4573,1717) 4553,1735.01
  Top w12: C653.1@4422.99,1327.05 4425,1325.04 v1(4425,1300) ; C653.1@4422.99,1327.05 v1(4425,1300) ; C653.1@4422.99,1327.05 v1(4425,1300)
  Top w15: C653.1@4421.83,1328.21 C653.1@4422.99,1327.05 ; C653.1@4421.83,1328.21 Q600.1@4369.35,1328.21 C653.1@4422.99,1327.05 ; C653.1@4421.83,1328.21 4379.29,1328.21 C653.1@4422.99,1327.05
  Bottom w10: v1(4425,1300) 4425,1323 4640.5,1538.5 4640.5,1597.54 4589.99,1648.05 4589.99,1700.01 v1(4573,1717)
CRTL21V_IP1001-2_1-CPU-RT0: C672.1 Q603.1 U609.16 | length 512.9
  Top w10: 5879,2068.05 5852.63,2068.05 U609.16@5852.63,2074.88 5879,2068.05 ; 5879,2068.05 5880.05,2067 5922.95,2067 5924,2068.05 ; 5924,2068.05 5933.99,2068.05 5937.76,2071.82 5942.76,2071.82 C672.1@5941.99,2072.05 5924,2068.05
  Top w20: Q603.1@5990.22,2012.82 C672.1@5941.99,2072.05 ; Q603.1@5996.67,2017.06 C672.1@5941.99,2072.05 ; Q603.1@6002.2,2012.62 5942.76,2060.28 ; Q603.1@6012.14,2012.62 5990.42,2012.62 5942.76,2060.28 ; C672.1@5941.99,2072.05 5942.76,2071.82 5942.76,2060.28 ; C672.1@5941.99,2072.05 5942.76,2060.28 ; C672.1@5941.99,2072.05 5942.76,2060.28 ; C672.1@5941.99,2072.05 5942.76,2060.28
CRTL21V_IP1001_1-CPU-RT0: C666.1 Q601.1 U607.16 | length 528.1
  Top w10: 4617.17,1649.45 U607.16@4578.63,1656.88 4578.63,1649.45 4659.39,1649.45 4663.76,1653.82 4668.76,1653.82 4668.99,1654.05 C666.1@4667.99,1654.05 4625.07,1649.45
  Top w20: 4773.52,1622.89 Q601.1@4847.69,1622.89 ; Q601.1@4857.63,1622.89 4688.15,1622.89 ; C666.1@4667.99,1654.05 4668.99,1654.05 4668.99,1642.05 ; C666.1@4667.99,1654.05 4668.99,1642.05 ; C666.1@4667.99,1654.05 4688.15,1622.89 ; C666.1@4667.99,1654.05 4668.99,1642.05 ; 4668.99,1642.05 4688.15,1622.89
D1_1-CPU-RT0: L4.1 U6.4 U6.6 | length 2384.1
  Top w4: 3278.5,2347.5 3279.08,2347.5 ; U6.6@3278.64,2328.93 3279.08,2347.5 ; U6.6@3282.67,2329.27 3279.08,2347.5 ; U6.6@3286.34,2330.4 3279.08,2347.5 ; U6.6@3289.7,2332.26 3279.08,2347.5 ; U6.6@3292.75,2334.92 3279.08,2347.5 ; U6.6@3296.18,2330.4 3279.08,2347.5
  Top w4.5: U6.4@3296.18,2255.6 3296.58,2255.2 3423,2255.2 3423,2335 L4.1@3420.01,2335 3410.01,2345 3408,2345 3408,2330 3296.58,2330 U6.6@3296.18,2330.4 ; U6.4@3306.02,2255.6 3329.37,2255.2 ; U6.6@3306.02,2330.4 3329.37,2330 ; U6.4@3306.18,2252.51 3329.37,2255.2 ; U6.6@3306.18,2327.31 3329.37,2330 ; U6.4@3306.28,2258.68 3329.37,2255.2 ; U6.6@3306.28,2333.48 3329.37,2330 ; U6.4@3307.13,2248.09 3329.37,2255.2 ; U6.6@3307.13,2322.89 3329.37,2330 ; U6.4@3307.39,2263.07 3329.37,2255.2 ; U6.6@3307.39,2337.87 3329.37,2330 ; L4.1@3387.98,2357.4 3340.35,2255.2 ; L4.1@3392.07,2355.39 3340.35,2255.2 ; L4.1@3396.07,2353.23 3340.35,2255.2 ; L4.1@3399.96,2350.91 3340.35,2255.2 ; L4.1@3402.93,2370.16 3364.98,2330 ; L4.1@3403.75,2348.44 3340.35,2255.2 ; L4.1@3406.25,2366.74 3364.98,2330 ; L4.1@3409.23,2363.09 3364.98,2330 ; L4.1@3409.55,2297.34 3364.98,2330 ; L4.1@3411.85,2359.26 3364.98,2330 ; L4.1@3412.2,2301.3 3364.98,2330 ; L4.1@3414.13,2355.25 3364.98,2330 ; L4.1@3414.47,2305.43 3364.98,2330 ; L4.1@3416.36,2309.67 3364.98,2330 ; L4.1@3417.87,2314.02 3364.98,2330 ; L4.1@3433.47,2318.77 3340.35,2255.2 ; L4.1@3435.95,2314.98 3340.35,2255.2 ; L4.1@3438.28,2311.09 3340.35,2255.2 ; L4.1@3440.45,2307.1 3340.35,2255.2 ; L4.1@3442.47,2303.01 3340.35,2255.2
DCDC_V33A: C54.1 R28.2 U1.B16 | length 732.1
  Top w4.5: U1.B16@2826.7,2176.36 2844.5,2180 ; U1.B16@2826.7,2183.64 2844.5,2180 ; R28.2@2963.55,2212.14 2962,2192.68 ; R28.2@2968,2211.25 2962,2192.68 ; R28.2@2971,2210 2962,2192.68 ; R28.2@2973,2210 2973,2203.68 2962,2192.68 ; R28.2@2973.75,2208.27 2962,2192.68 ; R28.2@2977.03,2205.13 2962,2192.68 ; 2844.5,2180 U1.B16@2826.33,2180 2844.5,2180 ; 2844.5,2180 2857.18,2192.68 2962,2192.68
  Top w5: R28.2@2972,2210 R28.2@2973,2210 ; R28.2@2974.12,2202.58 C54.1@2998,2210 ; R28.2@2974.12,2217.42 C54.1@2998,2210 ; C54.1@3004.48,2202.94 R28.2@2981.32,2215.18 ; C54.1@3004.48,2217.06 R28.2@2981.32,2204.82 ; C54.1@3007.42,2202.51 R28.2@2981.32,2204.82 ; C54.1@3007.42,2217.49 R28.2@2981.32,2215.18 ; R28.2@2973,2210 C54.1@3007,2210 ; R28.2@2973,2210 C54.1@2998,2210 ; R28.2@2981.32,2204.82 C54.1@3007,2210 ; R28.2@2981.32,2215.18 C54.1@3007,2210 ; R28.2@2982,2210 3005.88,2202.58 R28.2@2982,2210 ; R28.2@2982,2210 3005.88,2217.42 R28.2@2982,2210 ; R28.2@2982,2210 C54.1@3007,2210 ; R28.2@2982,2210 C54.1@3007,2210
DCDC_V33D: C29.1 C30.1 C51.1 R27.2 U1.A14 U6.2 | length 1332.1
  Top w4.5: C29.1@3233,2372 C29.1@3233,2379 ; C30.1@3267.41,2389 3267.41,2385 3268,2384.41 3268,2382 C30.1@3275.41,2388
  Top w6: U1.A14@2808.24,2234.29 2825.98,2252.03 3128,2252.03 C51.1@3128,2262 ; C51.1@3125.55,2268.09 3144.86,2275 ; C51.1@3126.25,2268.44 3096.81,2252.03 ; C51.1@3130.37,2255.13 3096.81,2252.03 ; C51.1@3134.3,2257.42 3144.86,2275 ; C29.1@3231.2,2385.76 3204.4,2375 ; C29.1@3233,2372 3230,2375 3195,2375 3148,2328 3148,2275 3144.86,2275 ; C29.1@3233,2379 3204.4,2375 ; C29.1@3233.12,2372 3204.4,2375 ; 3096.81,2252.03 C51.1@3129,2262 ; C51.1@3128,2262 3128,2258.14 3144.86,2275 ; C51.1@3128,2262 3123,2267 C51.1@3129,2262 ; C51.1@3129,2262 3144.86,2275
  Top w20: U6.2@3193.82,2293 3194.22,2292.6 3223,2292.6 ; 3233,2309 C29.1@3233,2379 ; C29.1@3233,2372 3233,2302.6 ; C30.1@3267.41,2389 3268,2389.59 C30.1@3268,2393 ; C30.1@3275.41,2386 C29.1@3233,2379 ; C30.1@3275.41,2388 C30.1@3268,2382 ; U6.2@3203.66,2293 3233,2302.6 ; U6.2@3203.66,2293 3223,2292.6 ; U6.2@3203.66,2293 3223,2292.6 ; 3223,2292.6 3233,2302.6 ; C29.1@3233,2379 3268,2379 C30.1@3268,2382 ; C30.1@3268,2382 C30.1@3268,2393 ; C30.1@3268,2393 R27.2@3268,2431 ; C30.1@3268,2393 R27.2@3268,2431 ; R27.2@3268,2431 3275.41,2390 R27.2@3268,2431
DDR_BA0: R97.2 U22.L2 | length 1152.4
  Top w4.5: v2@1477.76,2132.83 U22.L2@1492.61,2147.27 ; v2@1478.77,2133.84 U22.L2@1496.3,2143.83 ; v2@1478.87,2133.92 U22.L2@1497.07,2143.83 ; v2@1480.24,2134.67 U22.L2@1500.43,2139.32 ; v2@1485.75,2124.7 U22.L2@1500.43,2139.32 ; v2@1486.86,2125.8 U22.L2@1497.07,2143.83 ; v2@1486.97,2125.94 U22.L2@1496.3,2143.83 ; v2@1487.64,2127.16 U22.L2@1492.61,2147.27 ; v2(1482.3,2129.3) U22.L2@1496.3,2143.83 ; v2(1482.3,2129.3) U22.L2@1500.43,2139.32 ; v2(1482.3,2129.3) U22.L2@1492.61,2147.27 ; v2(1482.3,2129.3) U22.L2@1497.07,2143.83 ; U22.L2@1496.3,2143.83 U22.L2@1497.07,2143.83
  Bottom w4.5: v2@1478.81,2124.73 1497.6,2114 ; v2(1482.3,2129.3) 1497.6,2114 ; v2@1486.87,2132.79 1497.6,2114 ; R97.2@2054.81,1813.57 2033.16,1824 ; R97.2@2056.38,1817.81 2033.16,1824 ; R97.2@2056.71,1828.74 2033.16,1824 ; R97.2@2057,1821 2033.16,1824 ; R97.2@2057.19,1824.24 2033.16,1824 ; R97.2@2058,1821 2058,1823 2057,1824 1974,1824 1968,1818 1762,1818 1579,2001 1579,2055 1520,2114 1497.6,2114
DDR_BA1: R98.2 U22.L3 | length 1011.8
  Top w4.5: v2@1509.09,2132.86 U22.L3@1524.14,2147.3 ; v2@1510.2,2133.94 U22.L3@1528.56,2143.83 ; v2@1511.56,2134.68 U22.L3@1531.9,2139.3 ; v2@1517.03,2124.68 U22.L3@1531.9,2139.3 ; v2@1518.14,2125.77 U22.L3@1528.56,2143.83 ; v2@1518.92,2127.11 U22.L3@1524.14,2147.3 ; v2(1513.6,2129.3) U22.L3@1528.56,2143.83 ; v2(1513.6,2129.3) U22.L3@1531.9,2139.3 ; v2(1513.6,2129.3) U22.L3@1524.14,2147.3
  Bottom w4.5: v2@1510.73,2124.32 1536.5,2112.8 ; v2@1517.42,2133.6 1536.5,2112.8 ; R98.2@1988.4,1867.58 1966.45,1859 ; R98.2@1989.05,1852.31 1966.45,1859 ; R98.2@1989.64,1863.23 1966.45,1859 ; R98.2@1989.91,1856.75 1966.45,1859 ; R98.2@1990,1860 1966.45,1859 ; R98.2@1991,1860 1990,1859 1736,1859 1589.3,2005.7 1589.3,2060 1520,2129.3 v2(1513.6,2129.3) 1536.5,2112.8
DDR_BA2: R827.2 U22.L1 | length 1304.5
  Top w4.5: v2@1440.92,2131.06 U22.L1@1461.39,2147.56 ; v2@1441.45,2131.53 U22.L1@1461.83,2143.83 ; v2@1441.86,2131.82 U22.L1@1465.45,2143.73 ; v2@1442.98,2132.38 U22.L1@1467.01,2138.34 ; v2@1448.21,2122.23 U22.L1@1467.01,2138.34 ; v2@1449.1,2122.97 U22.L1@1465.45,2143.73 ; v2@1449.53,2123.45 U22.L1@1461.83,2143.83 ; v2@1449.86,2123.93 U22.L1@1461.39,2147.56 ; U22.L1@1461.57,2147.78 v2@1446.87,2128.87 ; U22.L1@1468.54,2139.06 v2@1446.87,2128.87 ; v2(1445,2127) U22.L1@1461.83,2143.83 ; v2(1445,2127) U22.L1@1467.01,2138.34 ; v2(1445,2127) U22.L1@1461.39,2147.56 ; v2(1445,2127) U22.L1@1465.45,2143.73 ; v2@1446.87,2128.87 U22.L1@1465.57,2143.83 U22.L1@1461.83,2143.83
  Bottom w4.5: v2@1439.3,2126.25 1445,2105 ; v2(1445,2127) 1445,2105 ; v2@1450.7,2126.25 1445,2105 ; R827.2@1986.72,1681.36 1964.5,1689 ; R827.2@1986.72,1696.64 1964.5,1689 ; R827.2@1987.78,1685.76 1964.5,1689 ; R827.2@1987.78,1692.24 1964.5,1689 ; R827.2@1988,1689 1776,1689 1464,2001 1464,2086 1445,2105
DDR_CASN: R104.2 U22.L7 | length 683.9
  Top w4.5: v2@1662.56,2128.15 U22.L7@1659.15,2147.06 ; v2@1664.49,2125.45 U22.L7@1651.32,2139.22 ; v2@1669.99,2135.39 U22.L7@1651.32,2139.22 ; v2@1672.65,2133.38 U22.L7@1659.15,2147.06 ; U22.L7@1651.32,2139.22 v2@1666,2132.38 ; U22.L7@1651.32,2139.22 v2(1668,2130) ; U22.L7@1654.55,2143.83 v2@1666,2132.38 ; U22.L7@1654.55,2143.83 v2@1666,2132.38 ; U22.L7@1654.55,2143.83 1663.33,2126.65 U22.L7@1654.55,2143.83 ; U22.L7@1654.55,2143.83 1671.48,2134.58 U22.L7@1654.55,2143.83 ; U22.L7@1654.55,2143.83 v2(1668,2130) ; U22.L7@1654.55,2143.83 v2(1668,2130) ; U22.L7@1659.15,2147.06 v2@1666,2132.38 ; U22.L7@1659.15,2147.06 v2(1668,2130) ; v2@1666,2132.38 1666,2132 v2(1668,2130)
  Bottom w4.5: v2@1664.46,2125.47 1684.75,2113.25 ; v2(1668,2130) 1684.75,2113.25 ; v2@1672.53,2133.54 1684.75,2113.25 ; R104.2@1897.13,2112.2 1882,2102 ; R104.2@1899.18,2108.15 1882,2102 ; R104.2@1899.62,2097.26 1882,2102 ; R104.2@1900,2105 1882,2102 ; R104.2@1900.25,2101.76 1882,2102 ; R104.2@1901,2105 1898,2102 1882,2102 ; 1684.75,2113.25 1704.75,2113.25 1705,2113 1712,2113 1723,2102 1811,2102 1812,2103 1881,2103 1882,2102
DDR_CLK_N_1-CPU-RT0: R100.1 U1.P2 | length 729.8
  Top w4.5: R100.1@1999.46,2236.24 2029.68,2240 ; R100.1@2000.35,2231.82 2029.68,2240 ; R100.1@2002.75,2225.79 2029.68,2240 ; R100.1@2005.15,2221.96 2029.68,2240 ; U1.P2@2355.49,2212.55 2337.81,2216.19 ; U1.P2@2355.49,2219.83 2337.81,2216.19 ; R100.1@2001.39,2228.74 2000.39,2228.74 2011.65,2240 ; R100.1@2001.39,2228.74 2011.65,2240 ; R100.1@2001.39,2228.74 2029.68,2240 ; R100.1@2001.39,2228.74 2011.65,2240 ; 2011.65,2240 2314,2240 2337.81,2216.19 ; 2011.65,2240 1997.18,2235.24 2011.65,2240 ; 2011.65,2240 2008.26,2225.14 2011.65,2240 ; 2011.65,2240 1999.23,2231.17 2011.65,2240 ; 2011.65,2240 2004.01,2226.82 2011.65,2240 ; 2337.81,2216.19 U1.P2@2355.86,2216.19 2337.81,2216.19
DDR_CLK_P_1-CPU-RT0: R99.1 U1.P1 | length 486.5
  Top w4.5: R99.1@1996.99,2257.71 2015,2250 ; R99.1@1999.25,2261.65 2015,2250 ; R99.1@2003.9,2266.15 2015,2250 ; R99.1@2007.92,2268.27 2015,2250 ; U1.P1@2334.94,2231.96 2324.04,2248.01 U1.P1@2340.09,2237.1 ; U1.P1@2337.76,2234.29 2322.05,2250 2015,2250 ; 2015,2250 2000.91,2264.09 R99.1@2001.39,2264.09 2015,2250
DDR_CSN: R106.2 U22.L8 | length 402
  Top w4.5: U22.L8@1686.04,2143.83 1700.83,2143.83 ; U22.L8@1687.11,2138.31 1700.83,2143.83 ; U22.L8@1687.11,2149.35 1700.83,2143.83 ; v2@1714.77,2150.6 1701,2144 ; v2@1715.54,2139.33 1701,2144 ; 1700.83,2143.83 1701,2144 ; 1701,2144 1716.24,2144 v2(1716.24,2145.04) 1701,2144
  Bottom w4.5: v2(1716.24,2145.04) 1716.24,2145.24 v2@1717,2146
  Bottom w5: v2(1716.24,2145.04) 1741.28,2146 ; v2@1716.63,2150.53 1741.28,2146 ; v2@1717,2146 1824,2146 1833,2137 R106.2@1832,2137 1800.54,2146 ; v2@1717.05,2139.6 1741.28,2146 ; R106.2@1829.12,2130.07 1800.54,2146 ; R106.2@1833.22,2144.4 1800.54,2146
DDR_IO_VREF: C70.1 C820.2 C821.1 R812.2 R813.1 U1.L5 | length 2042.7
  Top w8: U1.L5@2464.43,2216.19 v2(2480.5,2216.4) U1.L5@2464.43,2216.19
  Bottom w8: R812.2@2149.35,2346.99 C820.2@2183,2342 ; R812.2@2149.7,2335.04 C820.2@2183,2342 ; C820.2@2182.46,2335.2 R812.2@2150.33,2346.85 ; C820.2@2182.46,2346.8 R812.2@2150.3,2335.17 ; C820.2@2183.09,2335.07 C821.1@2216.1,2333.07 ; C820.2@2183.3,2335.04 R812.2@2149.97,2342 ; C820.2@2183.47,2335.02 R812.2@2149.96,2341.03 ; C820.2@2183.48,2346.98 R812.2@2149.96,2341.03 ; C820.2@2183.65,2346.99 R812.2@2149.97,2342 ; C820.2@2183.82,2347 C821.1@2216.82,2345 ; C820.2@2184.18,2335 C821.1@2217,2339 ; C820.2@2184.5,2335.02 R812.2@2150.3,2335.17 ; C820.2@2184.5,2346.98 R812.2@2150.33,2346.85 ; C820.2@2184.58,2335.03 C821.1@2215,2341 ; C820.2@2184.58,2346.97 C821.1@2215,2341 ; C820.2@2184.9,2346.93 C821.1@2217,2339 ; C820.2@2185.26,2335.13 C821.1@2216.82,2345 ; C820.2@2185.96,2346.67 C821.1@2216.1,2333.07 ; C821.1@2216.2,2344.95 R813.1@2250.42,2346.53 ; C821.1@2216.86,2333 R813.1@2250.86,2335.23 ; C821.1@2217.2,2345 R813.1@2250.96,2340.88 ; C821.1@2217.53,2333.02 2251,2339 C821.1@2217.53,2344.98 ; C821.1@2217.86,2333.06 R813.1@2250.96,2340.88 ; C821.1@2218.19,2344.88 R813.1@2250.86,2335.23 ; C821.1@2218.83,2333.28 R813.1@2250.42,2346.53 ; R813.1@2252.12,2346.94 C821.1@2218.88,2339 ; R813.1@2252.82,2335 C821.1@2218.88,2339 ; R813.1@2253.35,2335.01 2287.04,2340 ; R813.1@2253.7,2346.96 2287.04,2340 ; C70.1@2496.08,2219.57 2482,2245 ; C70.1@2505.11,2227.37 2482,2245 ; R812.2@2149.96,2341.03 C820.2@2184,2341 ; R812.2@2149.97,2342 C820.2@2184,2341 ; R812.2@2150.3,2335.17 C820.2@2184,2341 ; R812.2@2150.33,2346.85 C820.2@2184,2341 ; C820.2@2183,2342 2149,2342 R812.2@2149,2341 C820.2@2183,2342 ; C820.2@2183,2342 C820.2@2184,2341 ; C820.2@2184,2341 C821.1@2215,2341 ; C820.2@2184,2341 C821.1@2216.1,2333.07 ; C820.2@2184,2341 C821.1@2216.82,2345 ; C820.2@2184,2341 C821.1@2217,2339 ; C821.1@2215,2341 C821.1@2217,2339 ; C821.1@2217,2339 2252,2339 R813.1@2253,2340 ; C821.1@2217,2339 R813.1@2250.86,2335.23 ; C821.1@2217,2339 R813.1@2250.42,2346.53 ; C821.1@2217,2339 R813.1@2250.96,2340.88 ; C821.1@2218.88,2339 R813.1@2253,2341 ; R813.1@2253,2340 R813.1@2253,2341 ; R813.1@2253,2340 2424,2340 2482,2282 2482,2245 ; R813.1@2253,2341 2287.04,2340 ; 2482,2245 2501,2226 C70.1@2501,2223 2482,2245
  Bottom w10: v2(2480.5,2216.4) 2495,2216.4 2495,2217 C70.1@2501,2223 v2(2480.5,2216.4)
DDR_MCKE: R101.2 U22.K2 | length 1200.9
  Top w4.5: v2@1474.85,2170.81 U22.K2@1493.1,2179.32 ; v2@1475.8,2171.31 U22.K2@1493,2175.33 ; v2@1476.2,2171.46 U22.K2@1497.07,2175.33 ; v2@1477.62,2171.74 U22.K2@1499.58,2170.29 ; v2@1479.85,2160.56 U22.K2@1499.58,2170.29 ; v2@1481.2,2161.22 U22.K2@1497.07,2175.33 ; v2@1481.79,2161.68 U22.K2@1493,2175.33 ; v2@1482.38,2162.27 U22.K2@1493.1,2179.32 ; v2(1478,2166) 1481.67,2166 v2@1482.67,2165 ; v2(1478,2166) U22.K2@1493,2175.33 ; v2(1478,2166) U22.K2@1499.58,2170.29 ; v2(1478,2166) U22.K2@1493.1,2179.32 ; v2(1478,2166) U22.K2@1497.07,2175.33 ; v2@1482.67,2165 U22.K2@1493,2175.33 ; v2@1482.67,2165 U22.K2@1499.58,2170.29 ; v2@1482.67,2165 U22.K2@1493.1,2179.32 ; v2@1482.67,2165 U22.K2@1497.07,2175.33 ; U22.K2@1493,2175.33 U22.K2@1497.07,2175.33
  Bottom w4.5: v2@1474.38,2161.53 1497.55,2146.45 v2@1482.47,2169.62 ; v2(1478,2166) 1498,2146 1519,2146 1600,2065 1600,2010 1730,1880 R101.2@2059,1880 ; R101.2@2057.72,1872.36 2035.5,1880 ; R101.2@2057.72,1887.64 2035.5,1880 ; R101.2@2058.78,1876.76 2035.5,1880 ; R101.2@2058.78,1883.24 2035.5,1880
DDR_MDQM0: R95.2 U22.F3 | length 1671.1
  Top w4.5: v2(1513,2190.8) 1539.6,2190.8 1545,2184 1545,1938 1632,1851 1996,1851 2130,1985 2130,1992.14 R95.2@2129.67,1991.81 2115.34,1970.34 ; v2@1513.7,2185.09 1536.5,2190.8 v2@1513.7,2196.51 ; v2@1546.41,2307.08 U22.F3@1529.5,2295.77 ; v2@1546.71,2296.58 U22.F3@1529.18,2306.9 ; v2@1547.92,2307.57 U22.F3@1528.56,2301.31 ; v2@1548.06,2296.21 U22.F3@1529.15,2301.9 ; v2@1548.06,2307.59 U22.F3@1529.15,2301.9 ; v2@1548.25,2296.19 U22.F3@1528.56,2301.31 ; v2@1549.51,2307.62 U22.F3@1529.18,2306.9 ; v2@1549.84,2296.23 U22.F3@1529.5,2295.77 ; R95.2@2122.65,1995.1 2115.34,1970.34 ; R95.2@2126.86,1993.44 2115.34,1970.34 ; R95.2@2132.25,1989.84 2115.34,1970.34 ; R95.2@2135.4,1986.59 2115.34,1970.34 ; U22.F3@1528.56,2301.31 U22.F3@1529.15,2301.9 ; U22.F3@1528.56,2301.31 v2(1548.9,2301.9) ; U22.F3@1529.15,2301.9 v2(1548.9,2301.9) ; U22.F3@1529.18,2306.9 v2(1548.9,2301.9) ; U22.F3@1529.5,2295.77 v2(1548.9,2301.9)
  Bottom w4.5: v2@1509.66,2195.48 1530.5,2206.8 ; v2@1517.37,2187.06 1530.5,2206.8 ; v2@1545.96,2296.96 1567.5,2287.5 ; v2@1552.95,2305.98 1567.5,2287.5 ; 1530.5,2206.8 1530.5,2226.3 1567.5,2263.3 1567.5,2287.5 ; 1530.5,2206.8 1514.5,2190.8 v2(1513,2190.8) 1530.5,2206.8 ; 1567.5,2287.5 1553.1,2301.9 v2(1548.9,2301.9) 1567.5,2287.5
